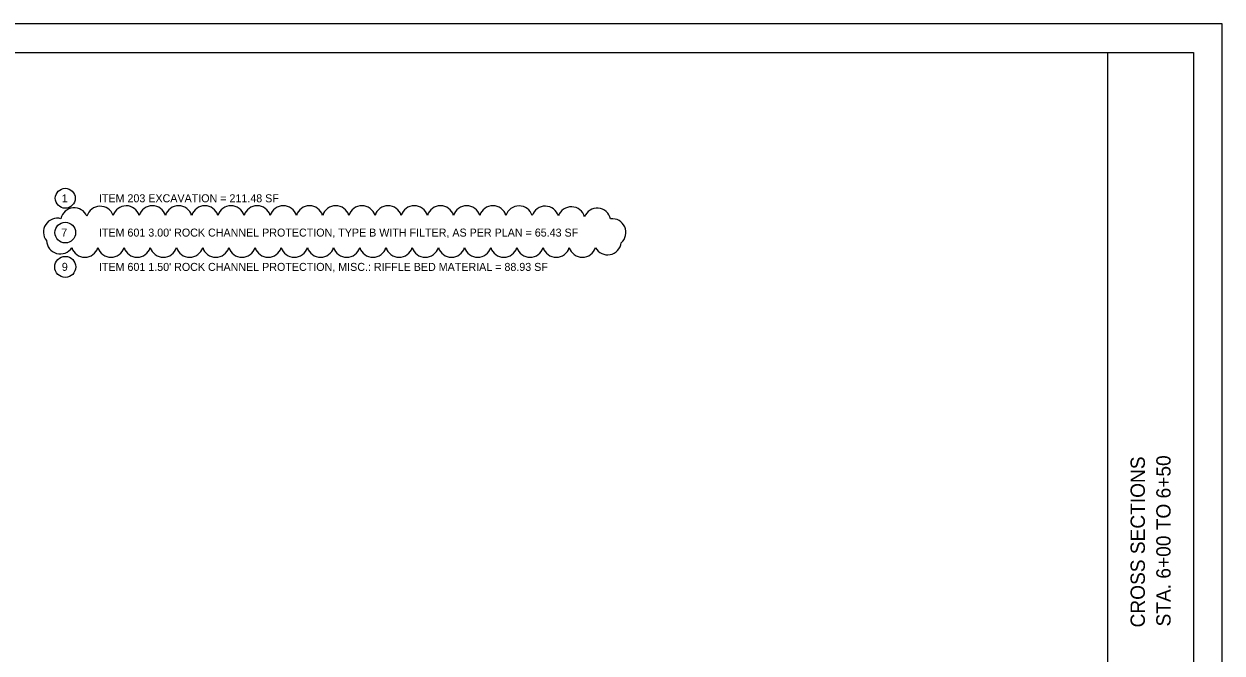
# Model space of a CAD drawing. Extents: x -433 to 34, y -184 to 22.
# Drawn here: x 13.04 to 34, y 11 to 22 of the extents above; entities that cross this region are included whole.
import ezdxf

# ---------------------------------------------------------------- set-up
doc = ezdxf.new("R2010")
doc.units = 0
for name, color, linetype in [('CS-ALGN-TEXT', 7, 'Continuous'), ('CS-ANNO', 7, 'Continuous'), ('CS-ANNO-MATC', 7, 'Continuous'), ('CS-ANNO-MATC-TEXT', 7, 'Continuous')]:
    doc.layers.add(name, color=color, linetype=linetype)

msp = doc.modelspace()

# ---------------------------------------------------------------- linework, layer by layer
at = {"layer": 'CS-ANNO'}
msp.add_lwpolyline([(0, 0), (34, 0), (34, 22), (0, 22)], close=True, dxfattribs=at)
at = {"layer": 'CS-ANNO-MATC'}
msp.add_line((32, 0.5), (32, 21.5), dxfattribs=at)
msp.add_lwpolyline([(1.5, 21.5), (33.5, 21.5), (33.5, 0.5), (1.5, 0.5)], close=True, dxfattribs=at)
at = {"layer": 'CS-ANNO-MATC-TEXT'}
for centre, radius in [((13.763, 18.952), 0.174), ((13.763, 18.352), 0.181), ((13.763, 17.752), 0.184)]:
    msp.add_circle(centre, radius, dxfattribs=at)
for centre, start, end in [((13.921, 18.545), 23.0018, 168.0018), ((14.373, 18.573), 19.1995, 164.1995), ((14.829, 18.58), 17.6773, 162.6773), ((15.287, 18.581), 17.5, 162.5), ((15.745, 18.581), 17.5, 162.5), ((16.204, 18.581), 17.5, 162.5), ((16.662, 18.581), 17.5, 162.5), ((17.12, 18.581), 17.5, 162.5), ((17.578, 18.581), 17.5, 162.5), ((18.036, 18.581), 17.5, 162.5), ((18.495, 18.581), 17.5, 162.5), ((18.953, 18.581), 17.5, 162.5), ((19.411, 18.581), 17.5, 162.5), ((19.869, 18.581), 17.5, 162.5), ((20.327, 18.581), 17.5, 162.5), ((20.785, 18.581), 17.5, 162.5), ((21.244, 18.581), 17.4674, 162.4674), ((21.701, 18.579), 17.1392, 162.1392), ((22.159, 18.574), 16.5796, 161.5796), ((22.616, 18.563), 15.6057, 160.6057), ((23.07, 18.538), 13.0764, 158.0764), ((13.621, 18.363), 74.226, 219.226), ((23.331, 18.354), 311.4536, 96.4536), ((13.675, 18.219), 181.9141, 326.9141), ((14.105, 18.161), 197.5, 342.5), ((14.563, 18.161), 197.5, 342.5), ((15.021, 18.161), 197.5, 342.5), ((15.48, 18.161), 197.5, 342.5), ((15.938, 18.161), 197.5, 342.5), ((16.396, 18.161), 197.5, 342.5), ((16.854, 18.161), 197.5, 342.5), ((17.312, 18.161), 197.5, 342.5), ((17.77, 18.161), 197.5, 342.5), ((18.229, 18.161), 197.5, 342.5), ((18.687, 18.161), 197.5, 342.5), ((19.145, 18.161), 197.5, 342.5), ((19.603, 18.161), 197.5, 342.5), ((20.061, 18.161), 197.5, 342.5), ((20.52, 18.161), 197.5, 342.5), ((20.978, 18.161), 197.5, 342.5), ((21.436, 18.161), 197.5, 342.5), ((21.894, 18.161), 197.5, 342.5), ((22.352, 18.161), 197.5, 342.5), ((22.81, 18.161), 197.5001, 342.5001), ((23.251, 18.202), 208.2817, 353.2817)]:
    msp.add_arc(centre, 0.24, start, end, dxfattribs=at)

# ---------------------------------------------------------------- texts
at = {"layer": 'CS-ALGN-TEXT'}
for s, p in [('CROSS SECTIONS', (32.65, 11.447)), ('STA. 6+00 TO 6+50', (33.1, 11.465))]:
    msp.add_text(s, height=0.25, rotation=90, dxfattribs=at).set_placement(p)
at = {"layer": 'CS-ANNO-MATC-TEXT'}
for s, p in [('1', (13.702, 18.881)), ('ITEM 203 EXCAVATION = 211.48 SF', (14.352, 18.882)), ('7', (13.693, 18.283)), ("ITEM 601 3.00' ROCK CHANNEL PROTECTION, TYPE B WITH FILTER, AS PER PLAN = 65.43 SF", (14.352, 18.282)), ('9', (13.703, 17.683)), ("ITEM 601 1.50' ROCK CHANNEL PROTECTION, MISC.: RIFFLE BED MATERIAL = 88.93 SF", (14.352, 17.682))]:
    msp.add_text(s, height=0.14, dxfattribs=at).set_placement(p)

doc.saveas('drawing.dxf')
